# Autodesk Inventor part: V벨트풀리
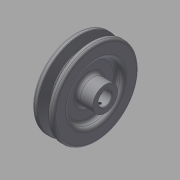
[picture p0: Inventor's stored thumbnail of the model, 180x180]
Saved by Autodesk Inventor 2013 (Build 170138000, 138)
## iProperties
Created: 2015-11
Part Number: V벨트풀리
Material: 강철, 탄소
Document SubType Name: Modeling
Designer: mduedu
Density: 7.87 g/cm^3
Mass: 425.947 g
Surface Area: 184.411 cm^2
Volume: 54.1228 cm^3
Author: mduedu
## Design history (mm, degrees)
sketch "스케치1"
  geometry: L1 (-9.5, 0)-(9.5, 0); L2 (0, 0)-(0, 37.7); L3 (-4.825, 37.7)-(-9.5, 37.7); L4 (-9.5, 37.7)-(-9.5, 0); L5 (0, 28.7)-(-2.074, 28.7); L6 (-2.074, 28.7)-(-4.825, 37.7); L7 (4.825, 37.7)-(9.5, 37.7); L8 (9.5, 37.7)-(9.5, 0); L9 (0, 28.7)-(2.074, 28.7); L10 (2.074, 28.7)-(4.825, 37.7); L11 (-9.5, 35)-(9.5, 35); 3 further points
  constraints: 22 end point, 7 point on line, 4 perpendicular, 3 symmetric about line, 1 coincident, 1 horizontal, 1 horizontal alignment, 1 midpoint, 1 vertical
  dimensions: "d0" = 19 distance of L1.start L1.end; "d2" = 75.4 diameter of L2.end L1 (derived); "d3" = 34 deg angle of L10 L6; "d4" = 6.3 distance between parallel lines of L11 L9; "d5" = 2.7 distance between parallel lines of L7 L11; "d6" = 8 distance of point (4, 35) point (-4, 35); "d7" = 70 diameter of L11 L1
revolve "회전1" sketch "스케치1" stored, may be unused: angle "d8" = 90 deg
sketch "스케치2"
  geometry: C1 r 24 at (0, 0); C2 r 11 at (0, 0); 1 further point
  constraints: 2 centre point, 2 coincident
  dimensions: "d9" = 48 diameter of C1; "d10" = 22 diameter of C2
extrude "돌출1" cut sketch "스케치2" distance "d11" = 6; taper "d12" = 0 deg
extrude "돌출3" join sketch "스케치2" distance "d37" = 8; taper "d38" = 0 deg
fillet "모깎기1" dims "d13" = 3
fillet "모깎기2" dims "d14" = 3
fillet "모깎기3" dims "d15" = 1, "d16" = 0.5, "d17" = 2
hole "구멍1" diameter "d20" = 12; stored, may be unused: countersink angle "d24" = 90 deg, drill point angle "d26" = 118 deg; dims "d21" = 6, "d22" = 4, "d23" = 2, "d25" = 8, "d58" = 10, "d59" = 10
sketch "스케치3"
  geometry: L1 (-2, 0)-(2, 0); L2 (2, 0)-(2, 7.8); L3 (2, 7.8)-(-2, 7.8); L4 (-2, 7.8)-(-2, 0); 2 further points
  constraints: 8 end point, 2 parallel, 1 coincident, 1 horizontal, 1 midpoint, 1 perpendicular
  dimensions: "d27" = 4 distance of L2.end L3.end; "d29" = 7.8 distance of L3.end L1.start
extrude "돌출2" cut sketch "스케치3" stored distance "d30" = 6; taper "d31" = 0 deg
node "작업 평면1"
sketch "스케치4"
  geometry: L1 (19, -27)-(19, 27) reference; 2 further points
  constraints: 1 horizontal alignment
  dimensions: "d52" = 22 distance from line of L1 point (-3, 0)
hole "구멍2" sketch "스케치4" at (-3, 0) diameter "d42" = 2.459; stored, may be unused: countersink angle "d46" = 90 deg, drill point angle "d48" = 118 deg; dims "d43" = 6, "d44" = 4, "d45" = 2, "d47" = 8
chamfer "모따기3" distance "d60" = 0.5; stored, may be unused: second distance "d61" = 2, angle "d62" = 45 deg
node "솔리드1"
mirror "대칭1"
